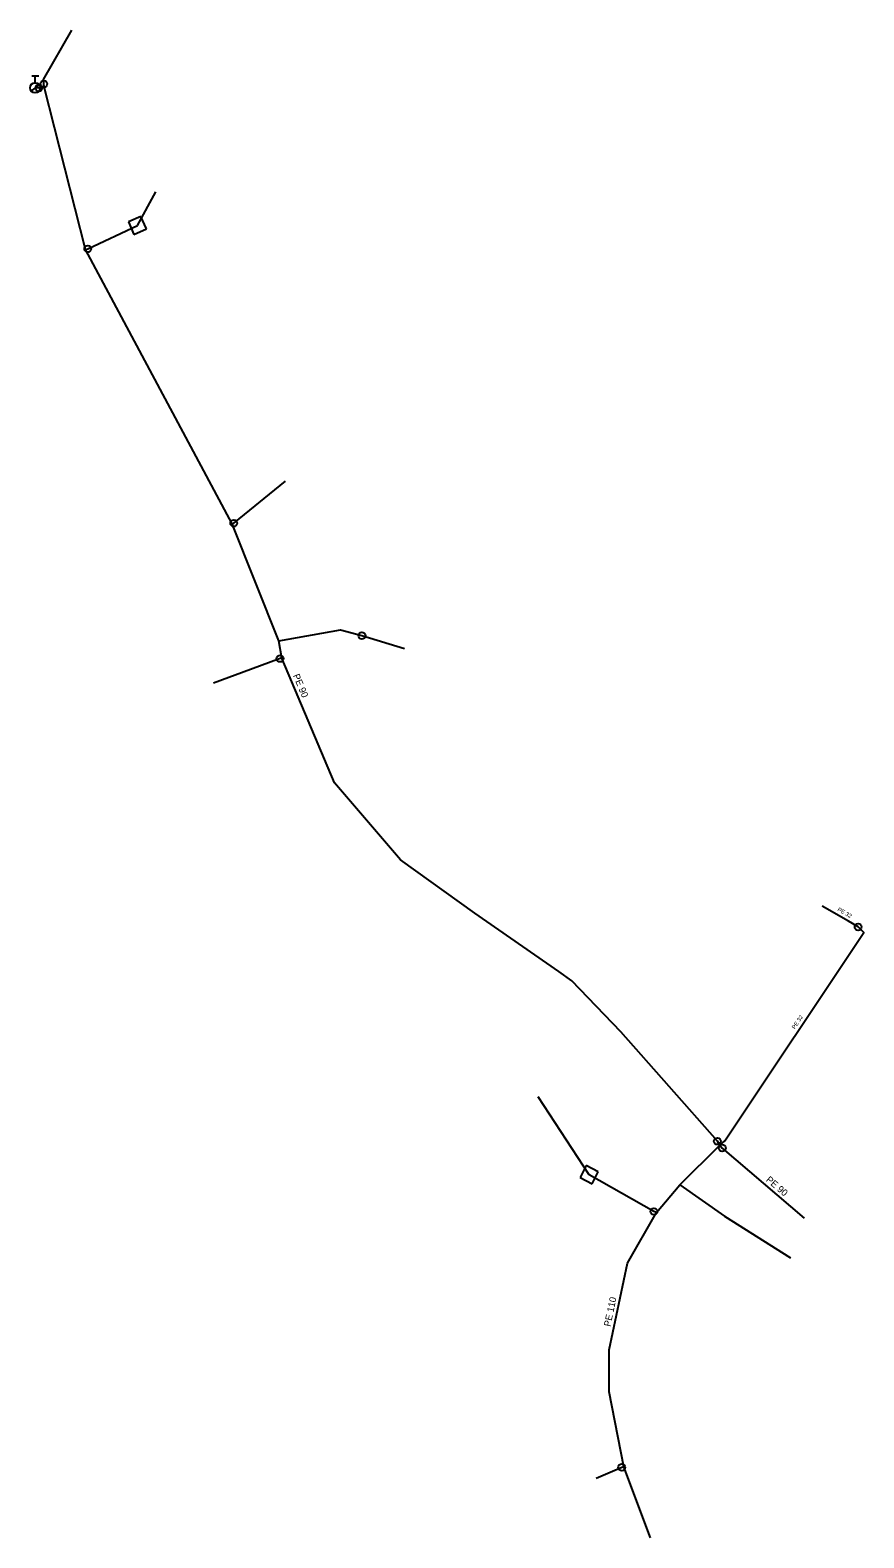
# Model space of a CAD drawing. Extents: x -681947 to -681511, y -1163527 to -1163073.
# Drawn here: x -681572.3 to -681511, y -1163307.6 to -1163196.7 of the extents above; entities that cross this region are included whole.
import ezdxf

# ---------------------------------------------------------------- set-up
doc = ezdxf.new("R2010")
doc.units = 0
for name, color, linetype in [('Hydranty', 7, 'Continuous'), ('Popis vodovodních řadů', 7, 'Continuous'), ('Vod přípojky-voda pitná', 7, 'Continuous'), ('Vodovodní řad', 7, 'Continuous'), ('Vodovodní šachty', 7, 'Continuous'), ('Vodovodní šoupata', 7, 'Continuous')]:
    doc.layers.add(name, color=color, linetype=linetype)

msp = doc.modelspace()

# ---------------------------------------------------------------- linework, layer by layer
at = {"layer": 'Hydranty'}
for p, q in [((-681572.16, -1163200.04), (-681571.66, -1163200.04)), ((-681571.91, -1163200.54), (-681571.91, -1163200.04)), ((-681572.2, -1163201.15), (-681571.61, -1163200.69))]:
    msp.add_line(p, q, dxfattribs=at)
msp.add_circle((-681571.91, -1163200.92), 0.375, dxfattribs=at)
at = {"layer": 'Vod přípojky-voda pitná'}
for points in [[(-681571.26, -1163200.84), (-681571.28, -1163200.63), (-681571.31, -1163200.3), (-681569.21, -1163196.67)], [(-681564.4, -1163211.04), (-681563.05, -1163208.57)], [(-681568.22, -1163212.81), (-681568.05, -1163212.77), (-681564.4, -1163211.04)], [(-681557.43, -1163233.01), (-681557.31, -1163232.96), (-681553.51, -1163229.86)], [(-681554, -1163241.61), (-681549.47, -1163240.8), (-681547.88, -1163241.23)], [(-681547.88, -1163241.23), (-681544.75, -1163242.17)], [(-681556.08, -1163243.73), (-681558.79, -1163244.74)], [(-681553.78, -1163242.9), (-681553.91, -1163242.92), (-681556.08, -1163243.73)], [(-681512.09, -1163262.24), (-681514.04, -1163261.13)], [(-681521.57, -1163278.72), (-681521.2, -1163278.41), (-681510.97, -1163263.08), (-681511.39, -1163262.67), (-681512.09, -1163262.24)], [(-681531.17, -1163280.9), (-681534.91, -1163275.17)], [(-681526.23, -1163283.68), (-681526.41, -1163283.61), (-681531.17, -1163280.9)], [(-681524.5, -1163281.65), (-681521.22, -1163283.96), (-681516.37, -1163287.03)], [(-681528.62, -1163302.39), (-681528.78, -1163302.44), (-681530.65, -1163303.27)]]:
    msp.add_lwpolyline(points, dxfattribs=at)
at = {"layer": 'Vodovodní řad'}
for points in [[(-681571.65, -1163200.93), (-681571.91, -1163200.92)], [(-681571.26, -1163200.84), (-681571.65, -1163200.93)], [(-681521.74, -1163278.44), (-681528.83, -1163270.4), (-681532.44, -1163266.63), (-681533.41, -1163265.95), (-681539.59, -1163261.66), (-681545.05, -1163257.73), (-681549.91, -1163252.06), (-681553.78, -1163242.9), (-681554, -1163241.61), (-681557.43, -1163233.01), (-681568.22, -1163212.81), (-681571.26, -1163200.84)], [(-681526.66, -1163307.63), (-681528.62, -1163302.39), (-681529.7, -1163296.89), (-681529.71, -1163293.78), (-681528.36, -1163287.41), (-681526.23, -1163283.68), (-681524.5, -1163281.65), (-681521.57, -1163278.72)], [(-681521.57, -1163278.72), (-681521.74, -1163278.44)], [(-681521.57, -1163278.72), (-681521.38, -1163278.94)], [(-681521.38, -1163278.94), (-681515.36, -1163284.11)]]:
    msp.add_lwpolyline(points, dxfattribs=at)
at = {"layer": 'Vodovodní šachty'}
for p, q in [((-681564.14, -1163210.38), (-681565.06, -1163210.78)), ((-681563.74, -1163211.3), (-681564.14, -1163210.38)), ((-681565.06, -1163210.78), (-681564.66, -1163211.7)), ((-681564.66, -1163211.7), (-681563.74, -1163211.3)), ((-681531.38, -1163280.23), (-681531.84, -1163281.11)), ((-681530.5, -1163280.69), (-681531.38, -1163280.23)), ((-681531.84, -1163281.11), (-681530.96, -1163281.57)), ((-681530.96, -1163281.57), (-681530.5, -1163280.69))]:
    msp.add_line(p, q, dxfattribs=at)
at = {"layer": 'Vodovodní šoupata'}
for centre in [(-681571.28, -1163200.63), (-681571.65, -1163200.93), (-681568.05, -1163212.77), (-681557.31, -1163232.96), (-681547.88, -1163241.23), (-681553.91, -1163242.92), (-681511.39, -1163262.67), (-681521.74, -1163278.44), (-681521.38, -1163278.94), (-681526.41, -1163283.61), (-681528.78, -1163302.44)]:
    msp.add_circle(centre, 0.25, dxfattribs=at)

# ---------------------------------------------------------------- texts
at = {"layer": 'Popis vodovodních řadů'}
for s, height, rotation, p in [('PE 90', 0.5, 292.9035, (-681552.97, -1163244.17)), ('PE 32', 0.3, 330.3501, (-681512.94, -1163261.47)), ('PE 32', 0.3, 56.2841, (-681516.04, -1163270.22)), ('PE 90', 0.5, 319.3506, (-681518.21, -1163281.34)), ('PE 110', 0.5, 78.0343, (-681529.61, -1163292.11))]:
    msp.add_text(s, height=height, rotation=rotation, dxfattribs=at).set_placement(p)

doc.saveas('drawing.dxf')
